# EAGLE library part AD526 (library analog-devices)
Monolithic Software Programmable Gain Amplifier Source: http://www.dscc.dla.mil/Downloads/MilSpec/Smd/90894.pdf
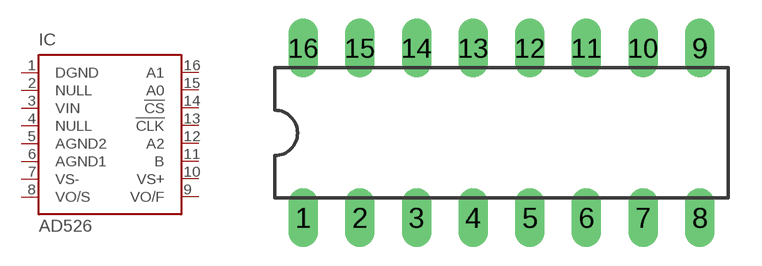
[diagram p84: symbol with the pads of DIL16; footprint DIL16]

Designator prefix IC

## AD526 (MF: ALTERA CORPORATION; MPN: AD526AD; OC_FARNELL: 402140; OC_NEWARK: 05F6913)  [DIL16]
1  DGND  in
2  NULL  in
3  VIN  in
4  NULL  in
5  AGND2  in
6  AGND1  in
7  VS-  in
8  VO/S  in
9  VO/F  in
10  VS+  in
11  B  in
12  A2  in
13  !CLK  in
14  !CS  in
15  A0  in
16  A1  in

## Footprint DIL16 (pad centres in mm)
Dual In Line Package
drill 0.813 long: 1 -8.89,-3.81; 2 -6.35,-3.81; 3 -3.81,-3.81; 4 -1.27,-3.81; 5 1.27,-3.81; 6 3.81,-3.81; 7 6.35,-3.81; 8 8.89,-3.81; 9 8.89,3.81; 10 6.35,3.81; 11 3.81,3.81; 12 1.27,3.81; 13 -1.27,3.81; 14 -3.81,3.81; 15 -6.35,3.81; 16 -8.89,3.81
